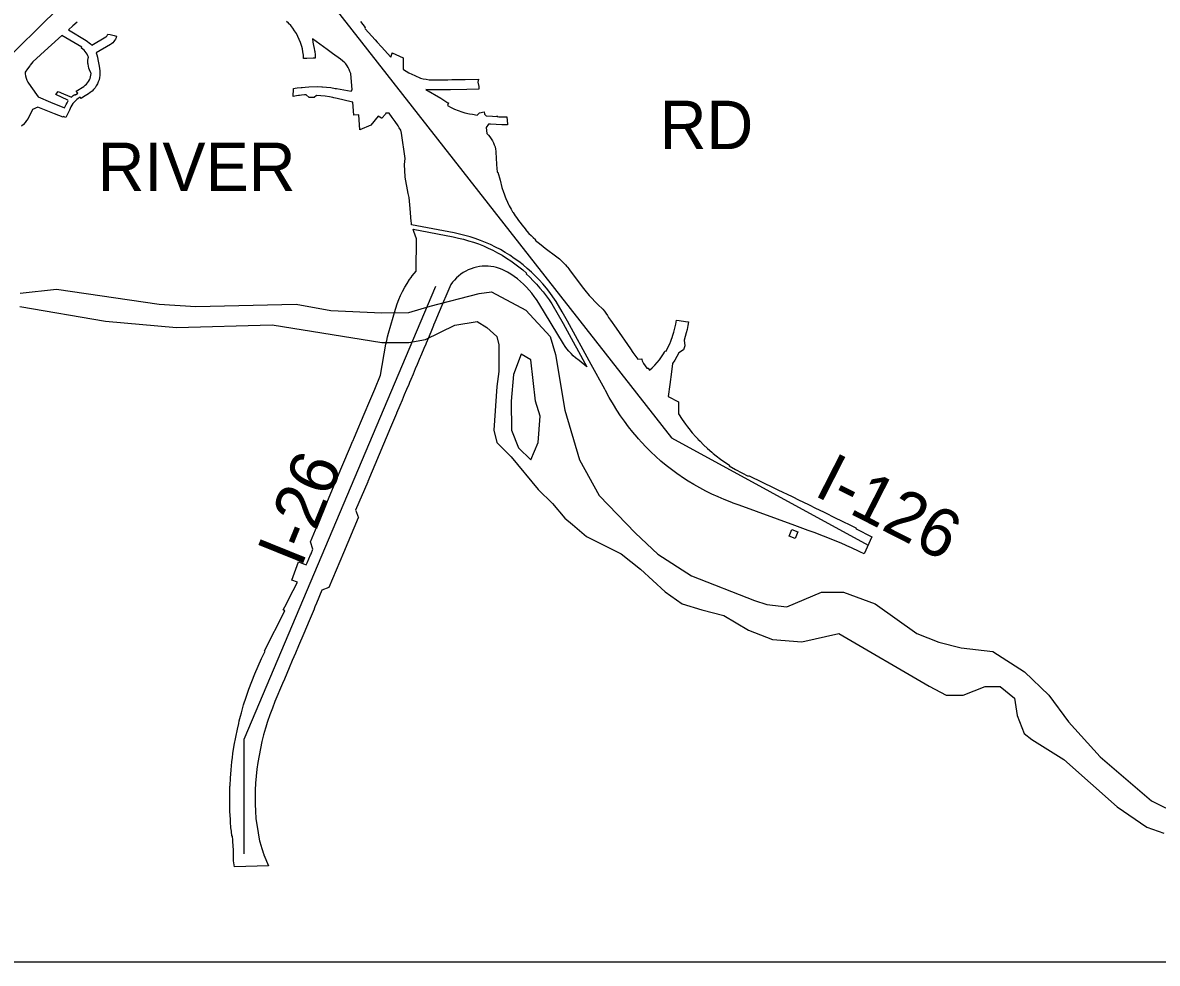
# Model space of a CAD drawing. Extents: x 1936118 to 1997618, y 780614 to 828614.
# Drawn here: x 1963667 to 1977726, y 788861 to 800516 of the extents above; entities that cross this region are included whole.
import ezdxf

# ---------------------------------------------------------------- set-up
doc = ezdxf.new("R2010")
doc.units = 0
for name, color, linetype in [('RD_EX_H2O_BlueLn', 7, 'Continuous'), ('RD_SHT_Misc3', 7, 'Continuous'), ('RD_SHT_Misc4', 7, 'Continuous'), ('RD_SHT_ShtClip', 7, 'Continuous')]:
    doc.layers.add(name, color=color, linetype=linetype)

msp = doc.modelspace()

# ---------------------------------------------------------------- linework, layer by layer
at = {"layer": 'RD_EX_H2O_BlueLn'}
for points in [[(1964341, 800523), (1964290, 800479), (1964235, 800428), (1964453, 800295), (1964472, 800282), (1964490, 800268), (1964507, 800252), (1964523, 800236), (1964697, 800340), (1964704, 800345), (1964710, 800351), (1964716, 800358), (1964720, 800366), (1964722, 800375), (1964751, 800369), (1964751, 800369), (1964799, 800357), (1964829, 800348), (1964825, 800335), (1964824, 800330), (1964816, 800313), (1964807, 800297), (1964796, 800282), (1964783, 800268), (1964769, 800256), (1964754, 800246), (1964579, 800141), (1964587, 800116), (1964593, 800089), (1964599, 800059), (1964614, 799977), (1964620, 799947), (1964623, 799919), (1964624, 799891), (1964623, 799863), (1964619, 799836), (1964613, 799809), (1964604, 799782), (1964593, 799757), (1964579, 799732), (1964564, 799709), (1964546, 799688), (1964527, 799668), (1964505, 799650), (1964483, 799634), (1964422, 799596), (1964391, 799576), (1964381, 799592), (1964356, 799577), (1964338, 799563), (1964320, 799548), (1964304, 799532), (1964290, 799514), (1964277, 799494), (1964266, 799474), (1964246, 799431), (1964204, 799340), (1964170, 799352), (1964168, 799347), (1964063, 799385), (1963958, 799426), (1963855, 799468), (1963788, 799442), (1963763, 799386), (1963749, 799357), (1963734, 799330), (1963716, 799304), (1963697, 799279), (1963676, 799256), (1963653, 799234)], [(1967853, 800530), (1967882, 800492), (1967913, 800455), (1967906, 800448), (1967913, 800440), (1968034, 800304), (1968060, 800275), (1968112, 800217), (1968228, 800087), (1968244, 800138), (1968245, 800140), (1968245, 800141), (1968380, 800081), (1968381, 800033), (1968382, 799943), (1968382, 799940), (1968385, 799937), (1968419, 799915), (1968454, 799895), (1968490, 799877), (1968528, 799861), (1968596, 799829), (1968631, 799821), (1968666, 799815), (1968702, 799810), (1968738, 799808), (1968764, 799808), (1968774, 799808), (1968934, 799810), (1968985, 799811), (1969151, 799814), (1969314, 799816), (1969308, 799777), (1969319, 799727), (1969320, 799691), (1969170, 799689), (1968967, 799686), (1968872, 799684), (1968776, 799683), (1968739, 799683), (1968701, 799685), (1968664, 799689), (1968849, 799579), (1968937, 799525), (1968944, 799521), (1968932, 799489), (1968975, 799466), (1969018, 799445), (1969063, 799426), (1969109, 799410), (1969147, 799398), (1969203, 799388), (1969239, 799381), (1969298, 799371), (1969328, 799399), (1969385, 799413), (1969388, 799387), (1969388, 799384), (1969390, 799382), (1969409, 799362), (1969489, 799356), (1969547, 799353), (1969569, 799351), (1969649, 799350), (1969665, 799350), (1969673, 799259), (1969674, 799251), (1969611, 799252), (1969604, 799252), (1969533, 799255), (1969463, 799260), (1969439, 799260), (1969412, 799217), (1969418, 799141), (1969438, 799121), (1969456, 799100), (1969473, 799078), (1969488, 799054), (1969500, 799029), (1969511, 799003), (1969520, 798977), (1969526, 798950), (1969530, 798922), (1969530, 798919), (1969536, 798828), (1969540, 798771), (1969540, 798768), (1969544, 798703), (1969546, 798677), (1969547, 798663), (1969555, 798663), (1969582, 798565), (1969606, 798474), (1969610, 798461), (1969620, 798428), (1969636, 798382), (1969644, 798359), (1969653, 798336), (1969673, 798292), (1969687, 798263), (1969695, 798248), (1969718, 798205), (1969737, 798174), (1969743, 798163), (1969770, 798123), (1969797, 798086), (1969799, 798083), (1969857, 798006), (1969892, 797961), (1969912, 797935), (1969915, 797932), (1969940, 797904), (1969966, 797878), (1969976, 797869), (1969993, 797853), (1970022, 797830), (1970016, 797822), (1970091, 797764), (1970143, 797724), (1970285, 797616), (1970319, 797588), (1970351, 797558), (1970382, 797527), (1970394, 797514), (1970411, 797494), (1970418, 797486), (1970418, 797485), (1970439, 797460), (1970439, 797459), (1970529, 797339), (1970564, 797292), (1970618, 797221), (1970631, 797203), (1970649, 797180), (1970668, 797158), (1970687, 797137), (1970795, 797026), (1970854, 796965), (1970875, 796941), (1970894, 796916), (1970912, 796889), (1970927, 796862), (1970952, 796830), (1971021, 796731), (1971198, 796476), (1971229, 796431), (1971288, 796347), (1971338, 796349), (1971339, 796344), (1971344, 796327), (1971350, 796311), (1971351, 796310), (1971360, 796294), (1971401, 796234), (1971418, 796236), (1971436, 796209), (1971468, 796240), (1971499, 796271), (1971529, 796304), (1971557, 796339), (1971583, 796375), (1971607, 796412), (1971621, 796435), (1971630, 796450), (1971639, 796446), (1971662, 796491), (1971684, 796537), (1971697, 796568), (1971704, 796584), (1971720, 796628), (1971721, 796632), (1971736, 796680), (1971749, 796730), (1971750, 796731), (1971760, 796779), (1971769, 796830), (1971802, 796825), (1971802, 796825), (1971881, 796813), (1971917, 796808), (1971910, 796762), (1971900, 796716), (1971889, 796671), (1971877, 796626), (1971862, 796582), (1971873, 796511), (1971857, 796463), (1971857, 796463), (1971798, 796426), (1971774, 796381), (1971748, 796336), (1971721, 796292), (1971707, 796190), (1971687, 796033), (1971667, 795886), (1971793, 795818), (1971793, 795669), (1971840, 795599), (1971880, 795543), (1971907, 795507), (1971921, 795488), (1971964, 795435), (1972009, 795384), (1972033, 795358), (1972034, 795357), (1972056, 795333), (1972057, 795332), (1972059, 795332), (1972060, 795332), (1972060, 795329), (1972104, 795285), (1972154, 795238), (1972206, 795193), (1972225, 795178), (1972259, 795150), (1972313, 795109), (1972369, 795069), (1972427, 795032), (1972423, 795025), (1972500, 794981), (1972578, 794938), (1972658, 794898), (1972662, 794907), (1972678, 794899), (1972973, 794754), (1973025, 794729), (1973200, 794643), (1973290, 794599), (1973335, 794577), (1973412, 794540), (1973489, 794502), (1973590, 794453), (1973752, 794373), (1973797, 794351), (1973951, 794276), (1973992, 794256), (1973993, 794244), (1974190, 794147), (1974096, 793935), (1974041, 793961), (1973930, 794012), (1973918, 794017), (1973817, 794061), (1973704, 794108), (1973590, 794154), (1973475, 794198), (1973400, 794225), (1973335, 794249), (1973333, 794249), (1973267, 794273), (1973236, 794285), (1972546, 794536), (1972471, 794564), (1972453, 794571), (1972360, 794607), (1972283, 794639), (1972207, 794674), (1972132, 794711), (1972058, 794751), (1971985, 794792), (1971913, 794836), (1971843, 794881), (1971797, 794913), (1971790, 794918), (1971774, 794929), (1971707, 794979), (1971641, 795031), (1971576, 795084), (1971513, 795140), (1971452, 795197), (1971393, 795256), (1971335, 795317), (1971298, 795359), (1971280, 795380), (1971226, 795444), (1971174, 795510), (1971124, 795577), (1971087, 795629), (1971075, 795645), (1971029, 795715), (1970986, 795787), (1970936, 795873), (1970888, 795960), (1970881, 795973), (1970711, 796282), (1970417, 796819), (1970351, 796932), (1970276, 797062), (1970238, 797118), (1970198, 797173), (1970156, 797227), (1970112, 797279), (1970067, 797329), (1970019, 797378), (1969970, 797426), (1969920, 797471), (1969868, 797515), (1969814, 797557), (1969759, 797596), (1969702, 797634), (1969645, 797670), (1969586, 797704), (1969526, 797736), (1969464, 797766), (1969402, 797793), (1969339, 797818), (1969275, 797841), (1969210, 797862), (1969145, 797881), (1969079, 797897), (1969012, 797911), (1968486, 798011), (1968484, 798036), (1968483, 798052), (1968469, 798213), (1968457, 798351), (1968444, 798401), (1968408, 798602), (1968407, 798605), (1968398, 798760), (1968408, 798833), (1968360, 799148), (1968354, 799183), (1968334, 799215), (1968320, 799237), (1968284, 799290), (1968247, 799342), (1968207, 799393), (1968168, 799393), (1968163, 799384), (1968119, 799332), (1968114, 799335), (1968074, 799357), (1967980, 799246), (1967845, 799187), (1967832, 799373), (1967772, 799369), (1967760, 799532), (1967738, 799537), (1967565, 799576), (1967523, 799585), (1967512, 799587), (1967469, 799596), (1967415, 799604), (1967361, 799610), (1967306, 799614), (1967281, 799590), (1967256, 799590), (1967217, 799590), (1967178, 799621), (1967166, 799622), (1967159, 799622), (1967124, 799619), (1967097, 799615), (1967084, 799613), (1967061, 799610), (1967019, 799603), (1967022, 799695), (1967021, 799699), (1967043, 799703), (1967069, 799707), (1967118, 799713), (1967130, 799714), (1967166, 799717), (1967215, 799720), (1967321, 799726), (1967376, 799723), (1967383, 799723), (1967432, 799718), (1967487, 799711), (1967541, 799702), (1967554, 799700), (1967736, 799666), (1967748, 799683), (1967732, 799886), (1967723, 799911), (1967713, 799936), (1967701, 799960), (1967688, 799983), (1967672, 800005), (1967661, 800019), (1967629, 800044), (1967604, 800062), (1967507, 800134), (1967441, 800183), (1967260, 800317), (1967262, 800273), (1967272, 800235), (1967280, 800196), (1967284, 800170), (1967286, 800157), (1967291, 800117), (1967293, 800078), (1967268, 800076), (1967190, 800073), (1967148, 800072), (1967145, 800113), (1967140, 800153), (1967133, 800193), (1967125, 800222), (1967123, 800232), (1967110, 800271), (1967095, 800309), (1967078, 800346), (1967059, 800381), (1967037, 800416), (1967014, 800449), (1966988, 800480), (1966963, 800508), (1966961, 800510), (1966938, 800532)], [(1963637, 797163), (1964087, 797216), (1965358, 797030), (1965812, 796999)], [(1968450, 796923), (1968718, 797004), (1969323, 797162)], [(1969323, 797162), (1969478, 797180), (1969903, 796952), (1970205, 796627), (1970270, 796406), (1970385, 795713), (1970567, 795101), (1970810, 794657), (1971260, 794191), (1971536, 793930), (1971953, 793664), (1972736, 793357)], [(1963634, 797000), (1964695, 796817), (1965572, 796739), (1966759, 796771), (1968119, 796555), (1968450, 796552), (1968660, 796592), (1969023, 796770), (1969298, 796812), (1969417, 796738), (1969543, 796629), (1969569, 796523), (1969569, 796193), (1969543, 796009), (1969506, 795468), (1969541, 795314), (1969720, 795138), (1970053, 794733), (1970232, 794557), (1970383, 794375)], [(1965812, 796999), (1967058, 797027), (1967484, 796951), (1968118, 796921), (1968450, 796923)], [(1969962, 795100), (1970053, 795316), (1970079, 795642), (1970022, 795826), (1969964, 796339), (1969845, 796407), (1969747, 796155), (1969721, 795827), (1969723, 795467), (1969811, 795246), (1969962, 795100)], [(1970383, 794375), (1970478, 794298), (1970655, 794151), (1971081, 793933), (1971322, 793746), (1971628, 793464), (1971838, 793316), (1972081, 793242), (1972354, 793172), (1972659, 792989), (1972958, 792874), (1973321, 792843), (1973780, 792949), (1974899, 792293), (1975109, 792184), (1975319, 792184), (1975594, 792292), (1975778, 792290), (1975956, 792147), (1975988, 791931), (1976076, 791709), (1976171, 791635), (1976566, 791388), (1977227, 790800), (1977595, 790548), (1977807, 790475)], [(1972736, 793357), (1972887, 793307)], [(1972887, 793307), (1973137, 793277), (1973565, 793461), (1973839, 793461), (1974231, 793317), (1974747, 792949), (1975021, 792840), (1975294, 792771), (1975688, 792726), (1976079, 792473), (1976383, 792182), (1976624, 791854), (1977019, 791420), (1977654, 790875), (1977996, 790703)]]:
    msp.add_lwpolyline(points, dxfattribs=at)
for points in [[(1963985, 800203), (1963795, 800031), (1963761, 799989), (1963755, 799981), (1963729, 799946), (1963697, 799902), (1963698, 799894), (1963699, 799882), (1963704, 799856), (1963711, 799830), (1963719, 799805), (1963730, 799781), (1963768, 799727), (1963858, 799597), (1964014, 799532), (1964185, 799459), (1964207, 799503), (1964218, 799525), (1964232, 799546), (1964228, 799558), (1964079, 799627), (1964108, 799662), (1964175, 799634), (1964272, 799594), (1964293, 799612), (1964315, 799628), (1964320, 799622), (1964349, 799641), (1964332, 799669), (1964424, 799727), (1964441, 799740), (1964457, 799754), (1964471, 799770), (1964484, 799787), (1964494, 799806), (1964503, 799825), (1964509, 799846), (1964513, 799867), (1964514, 799888), (1964511, 799896), (1964496, 799931), (1964487, 799954), (1964481, 799978), (1964477, 800003), (1964476, 800015), (1964475, 800020), (1964475, 800027), (1964476, 800052), (1964479, 800074), (1964479, 800076), (1964480, 800079), (1964481, 800086), (1964481, 800087), (1964481, 800087), (1964481, 800087), (1964481, 800088), (1964474, 800107), (1964466, 800126), (1964455, 800144), (1964442, 800160), (1964428, 800176), (1964412, 800189), (1964395, 800201), (1964401, 800211), (1964154, 800356)], [(1969547, 799360), (1969547, 799356), (1969545, 799356), (1969545, 799358), (1969545, 799360)], [(1969766, 797530), (1969816, 797492), (1969864, 797453), (1969911, 797412), (1969904, 797405), (1969950, 797363), (1969993, 797319), (1970005, 797307), (1970036, 797275), (1970076, 797228), (1970116, 797181), (1970153, 797132), (1970190, 797082), (1970198, 797070), (1970224, 797031), (1970364, 796789), (1970514, 796518), (1970529, 796489), (1970659, 796253), (1970564, 796329), (1970519, 796364), (1970490, 796389), (1970462, 796416), (1970435, 796444), (1970410, 796474), (1970388, 796505), (1970367, 796538), (1970062, 797040), (1970061, 797041), (1970034, 797084), (1970019, 797105), (1970005, 797125), (1969975, 797165), (1969942, 797203), (1969908, 797240), (1969873, 797275), (1969835, 797309), (1969797, 797341), (1969757, 797371), (1969715, 797400), (1969673, 797426), (1969641, 797443), (1969608, 797458), (1969575, 797471), (1969540, 797482), (1969505, 797490), (1969470, 797495), (1969434, 797499), (1969417, 797499), (1969401, 797499), (1969398, 797499), (1969362, 797498), (1969327, 797494), (1969291, 797487), (1969257, 797478), (1969223, 797467), (1969189, 797453), (1969157, 797437), (1969126, 797419), (1969096, 797399), (1969068, 797377), (1969041, 797353), (1969016, 797327), (1968993, 797300), (1968972, 797271), (1968947, 797213), (1968923, 797156), (1968899, 797098), (1968896, 797090), (1968829, 796932), (1968776, 796807), (1968759, 796766), (1968758, 796763), (1968741, 796724), (1968694, 796612), (1968666, 796545), (1968661, 796534), (1968637, 796478), (1968609, 796410), (1968581, 796343), (1968554, 796280), (1968531, 796225), (1968504, 796161), (1968477, 796096), (1968460, 796056), (1968450, 796033), (1968423, 795970), (1968395, 795903), (1968368, 795838), (1968341, 795774), (1968301, 795679), (1968299, 795675), (1968225, 795500), (1967943, 794830), (1967942, 794828), (1967793, 794475), (1967799, 794461), (1967821, 794401), (1967827, 794384), (1967826, 794381), (1967641, 793945), (1967462, 793518), (1967459, 793517), (1967376, 793485), (1967309, 793325), (1967289, 793278), (1967279, 793254), (1967277, 793251), (1967216, 793105), (1967149, 792947), (1967086, 792796), (1967047, 792704), (1967008, 792613), (1966969, 792521), (1966911, 792382), (1966888, 792329), (1966793, 792104), (1966761, 792023), (1966730, 791941), (1966702, 791859), (1966693, 791831), (1966693, 791830), (1966676, 791776), (1966653, 791692), (1966631, 791608), (1966613, 791523), (1966596, 791437), (1966582, 791351), (1966570, 791265), (1966561, 791178), (1966554, 791092), (1966550, 791005), (1966548, 790918), (1966548, 790831), (1966551, 790744), (1966556, 790657), (1966555, 790656), (1966585, 790477), (1966586, 790473), (1966602, 790379), (1966606, 790366), (1966607, 790364), (1966631, 790283), (1966642, 790246), (1966643, 790241), (1966654, 790209), (1966655, 790206), (1966713, 790067), (1966290, 790058), (1966278, 790131), (1966280, 790194), (1966279, 790258), (1966276, 790321), (1966273, 790366), (1966272, 790387), (1966269, 790438), (1966267, 790438), (1966259, 790438), (1966253, 790497), (1966248, 790540), (1966243, 790615), (1966241, 790642), (1966236, 790745), (1966235, 790763), (1966233, 790847), (1966234, 790907), (1966234, 790950), (1966236, 791052), (1966237, 791065), (1966242, 791155), (1966250, 791257), (1966260, 791359), (1966267, 791411), (1966273, 791461), (1966289, 791562), (1966307, 791663), (1966328, 791764), (1966344, 791833), (1966351, 791864), (1966367, 791925), (1966377, 791963), (1966405, 792062), (1966436, 792160), (1966469, 792257), (1966505, 792353), (1966543, 792448), (1966584, 792542), (1966627, 792636), (1966651, 792686), (1966672, 792728), (1966663, 792732), (1966915, 793230), (1966897, 793239), (1966936, 793315), (1966966, 793375), (1966967, 793377), (1967072, 793584), (1967003, 793609), (1967085, 793834), (1967158, 793808), (1967181, 793799), (1967193, 793822), (1967234, 793921), (1967240, 793934), (1967264, 793992), (1967232, 794085), (1967378, 794432), (1967401, 794486), (1967401, 794487), (1967623, 795013), (1967730, 795265), (1967755, 795326), (1967757, 795331), (1967778, 795379), (1967832, 795507), (1967853, 795558), (1967911, 795695), (1967956, 795802), (1968030, 795977), (1968102, 796148), (1968169, 796533), (1968178, 796579), (1968189, 796625), (1968201, 796669), (1968201, 796670), (1968288, 796965), (1968291, 796977), (1968309, 797031), (1968328, 797084), (1968350, 797136), (1968375, 797187), (1968401, 797237), (1968430, 797285), (1968461, 797333), (1968481, 797359), (1968494, 797378), (1968518, 797408), (1968542, 797438), (1968546, 797838), (1968515, 797929), (1968506, 797956), (1969003, 797862), (1969067, 797848), (1969130, 797833), (1969192, 797815), (1969254, 797796), (1969315, 797774), (1969376, 797750), (1969435, 797724), (1969494, 797696), (1969551, 797666), (1969608, 797634), (1969663, 797600), (1969715, 797566)], [(1973270, 794209), (1973240, 794126), (1973166, 794153), (1973196, 794236)]]:
    msp.add_lwpolyline(points, close=True, dxfattribs=at)
at = {"layer": 'RD_SHT_Misc4'}
for p, q in [((1966734, 801722), (1971705, 795370)), ((1956667, 793363), (1964119, 800706)), ((1966413, 791638), (1968788, 797250)), ((1971705, 795370), (1974143, 794041)), ((1966413, 790218), (1966413, 791638))]:
    msp.add_line(p, q, dxfattribs=at)
at = {"layer": 'RD_SHT_ShtClip'}
msp.add_lwpolyline([(1936683, 827674), (1979343, 827674), (1979343, 811384), (1997169, 811384), (1997169, 788874), (1947786, 788874), (1945387, 788861), (1936683, 788861)], close=True, dxfattribs=at)

# ---------------------------------------------------------------- texts
at = {"layer": 'RD_SHT_Misc3'}
for s, p in [('RD', (1971561, 798949)), ('RIVER', (1964596, 798430))]:
    msp.add_text(s, height=600, dxfattribs=at).set_placement(p)
for s, rotation, p in [('I-26', 68.0192, (1967116, 793752)), ('I-126', 333.0286, (1973455, 794667))]:
    msp.add_text(s, height=600, rotation=rotation, dxfattribs=at).set_placement(p)

doc.saveas('drawing.dxf')
